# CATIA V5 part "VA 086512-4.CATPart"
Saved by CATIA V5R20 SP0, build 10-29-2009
Part number: VA 086512-4
Revision: ANY
Definition: UNKNOWN
Nomenclature: VA 086512-4
Source: Unknown
Bounding box of the stored display mesh (mm): x -3.104 to 3.104, y 0 to 3, z -2.15 to 2.15
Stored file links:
  C:\Users\Utente\Desktop\IO LAVORO\3D X SITO CF\CUMSA\3D files VA\VA 086512\VA 086512-4.CATPart
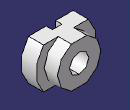
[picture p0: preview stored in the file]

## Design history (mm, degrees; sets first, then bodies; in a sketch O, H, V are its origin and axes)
Body1 "Cortar-Extruir2" (main body)
  Solid1: solid without history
